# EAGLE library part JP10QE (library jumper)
JUMPER
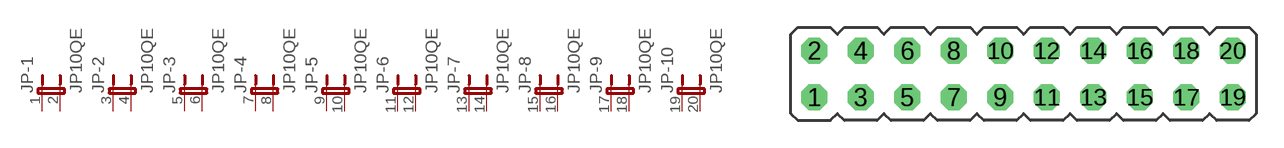
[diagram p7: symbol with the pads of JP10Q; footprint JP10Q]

Designator prefix JP; gates -1=JP2E -2=JP2E -3=JP2E -4=JP2E -5=JP2E -6=JP2E -7=JP2E -8=JP2E -9=JP2E -10=JP2E

## JP10QE  [JP10Q]
1  -1:1  pas
2  -1:2  pas
3  -2:1  pas
4  -2:2  pas
5  -3:1  pas
6  -3:2  pas
7  -4:1  pas
8  -4:2  pas
9  -5:1  pas
10  -5:2  pas
11  -6:1  pas
12  -6:2  pas
13  -7:1  pas
14  -7:2  pas
15  -8:1  pas
16  -8:2  pas
17  -9:1  pas
18  -9:2  pas
19  -10:1  pas
20  -10:2  pas

## Footprint JP10Q (pad centres in mm)
JUMPER
drill 0.914 octagon: 1 -11.43,-1.27; 2 -11.43,1.27; 3 -8.89,-1.27; 4 -8.89,1.27; 5 -6.35,-1.27; 6 -6.35,1.27; 7 -3.81,-1.27; 8 -3.81,1.27; 9 -1.27,-1.27; 10 -1.27,1.27; 11 1.27,-1.27; 12 1.27,1.27; 13 3.81,-1.27; 14 3.81,1.27; 15 6.35,-1.27; 16 6.35,1.27; 17 8.89,-1.27; 18 8.89,1.27; 19 11.43,-1.27; 20 11.43,1.27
